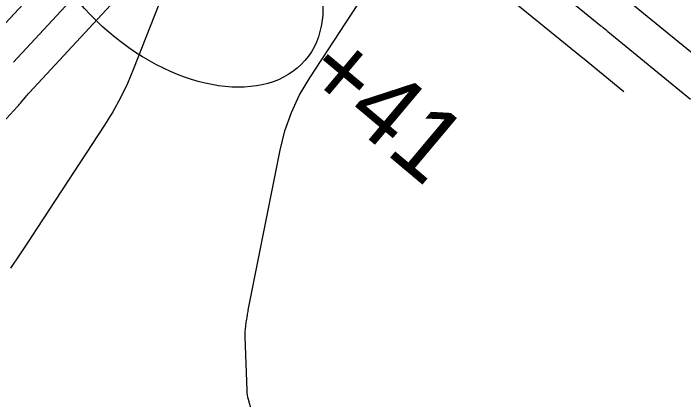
# Model space of a CAD drawing. Extents: x 1005228 to 1008882, y 1883389 to 1885754.
# Drawn here: x 1007741.8 to 1007796.7, y 1884651.8 to 1884683.5 of the extents above; entities that cross this region are included whole.
import ezdxf

# ---------------------------------------------------------------- set-up
doc = ezdxf.new("R2010")
doc.units = 0
for name, color, linetype in [('ATDIMS', 7, 'Continuous'), ('C-ANNO-NOTE', 7, 'Continuous'), ('R_Erosion', 7, 'Continuous'), ('S_BASELINE', 7, 'Continuous'), ('S_BRIDGE', 7, 'Continuous'), ('TSOBSTACLE', 7, 'Continuous')]:
    doc.layers.add(name, color=color, linetype=linetype)

msp = doc.modelspace()

# ---------------------------------------------------------------- linework, layer by layer
at = {"layer": 'ATDIMS'}
msp.add_lwpolyline([(1007783.28, 1884687.915), (1007789.948, 1884682.459), (1007789.994, 1884682.421), (1007790.04, 1884682.383), (1007790.086, 1884682.346), (1007790.132, 1884682.308), (1007790.315, 1884682.157), (1007790.361, 1884682.12), (1007790.407, 1884682.082), (1007790.453, 1884682.044), (1007790.499, 1884682.007), (1007797.299, 1884676.442)], dxfattribs=at)
at = {"layer": 'C-ANNO-NOTE'}
for points in [[(1007734.266, 1884667.327), (1007742.104, 1884675.836), (1007742.19, 1884675.931), (1007742.275, 1884676.027), (1007742.358, 1884676.124), (1007742.44, 1884676.222), (1007742.766, 1884676.619), (1007742.848, 1884676.717), (1007742.932, 1884676.814), (1007743.017, 1884676.91), (1007743.103, 1884677.005), (1007752.888, 1884687.566)], [(1007748.546, 1884686.784), (1007742.112, 1884679.839), (1007741.773, 1884679.468)], [(1007754.355, 1884685.908), (1007751.629, 1884678.922), (1007751.124, 1884677.723), (1007750.56, 1884676.555), (1007749.936, 1884675.418), (1007749.251, 1884674.312), (1007743.699, 1884665.838), (1007742.984, 1884664.754), (1007742.263, 1884663.675), (1007741.535, 1884662.6)], [(1007761.243, 1884651.12), (1007761.051, 1884651.828), (1007761.008, 1884652.006), (1007760.975, 1884652.186), (1007760.953, 1884652.367), (1007760.94, 1884652.549), (1007760.767, 1884656.958), (1007760.765, 1884657.068), (1007760.766, 1884657.178), (1007760.772, 1884657.289), (1007760.781, 1884657.399), (1007760.824, 1884657.839), (1007760.836, 1884657.949), (1007760.85, 1884658.058), (1007760.865, 1884658.168), (1007760.882, 1884658.277), (1007760.955, 1884658.717), (1007760.974, 1884658.827), (1007760.993, 1884658.937), (1007761.013, 1884659.046), (1007761.035, 1884659.155), (1007763.635, 1884672.269), (1007764.026, 1884673.842), (1007764.562, 1884675.356), (1007765.244, 1884676.809), (1007766.071, 1884678.203), (1007770.025, 1884684.196)]]:
    msp.add_lwpolyline(points, dxfattribs=at)
at = {"layer": 'R_Erosion'}
msp.add_ellipse((1007755.31, 1884688.562), major_axis=(10.366, -8.953), ratio=0.638788, dxfattribs=at)
at = {"layer": 'S_BRIDGE'}
msp.add_lwpolyline([(1007746.183, 1884688.137), (1007741.12, 1884682.672)], dxfattribs=at)
at = {"layer": 'TSOBSTACLE'}
for points in [[(1007791.828, 1884677.045), (1007788.425, 1884679.83), (1007788.359, 1884679.885), (1007781.223, 1884685.724), (1007781.164, 1884685.772), (1007781.077, 1884685.844), (1007781.048, 1884685.868), (1007774.066, 1884691.581), (1007774.021, 1884691.617), (1007773.977, 1884691.654), (1007773.932, 1884691.69), (1007773.888, 1884691.726), (1007773.711, 1884691.872), (1007773.622, 1884691.945), (1007773.534, 1884692.017), (1007767.644, 1884696.843), (1007767.205, 1884697.203), (1007766.766, 1884697.562), (1007766.327, 1884697.922), (1007765.889, 1884698.281), (1007763.256, 1884700.439)], [(1007798.897, 1884679.008), (1007792.573, 1884684.183)]]:
    msp.add_lwpolyline(points, dxfattribs=at)

# ---------------------------------------------------------------- texts
at = {"layer": 'S_BASELINE'}
msp.add_text('+41', height=6, rotation=320, dxfattribs=at).set_placement((1007765.185, 1884677.935))

doc.saveas('drawing.dxf')
